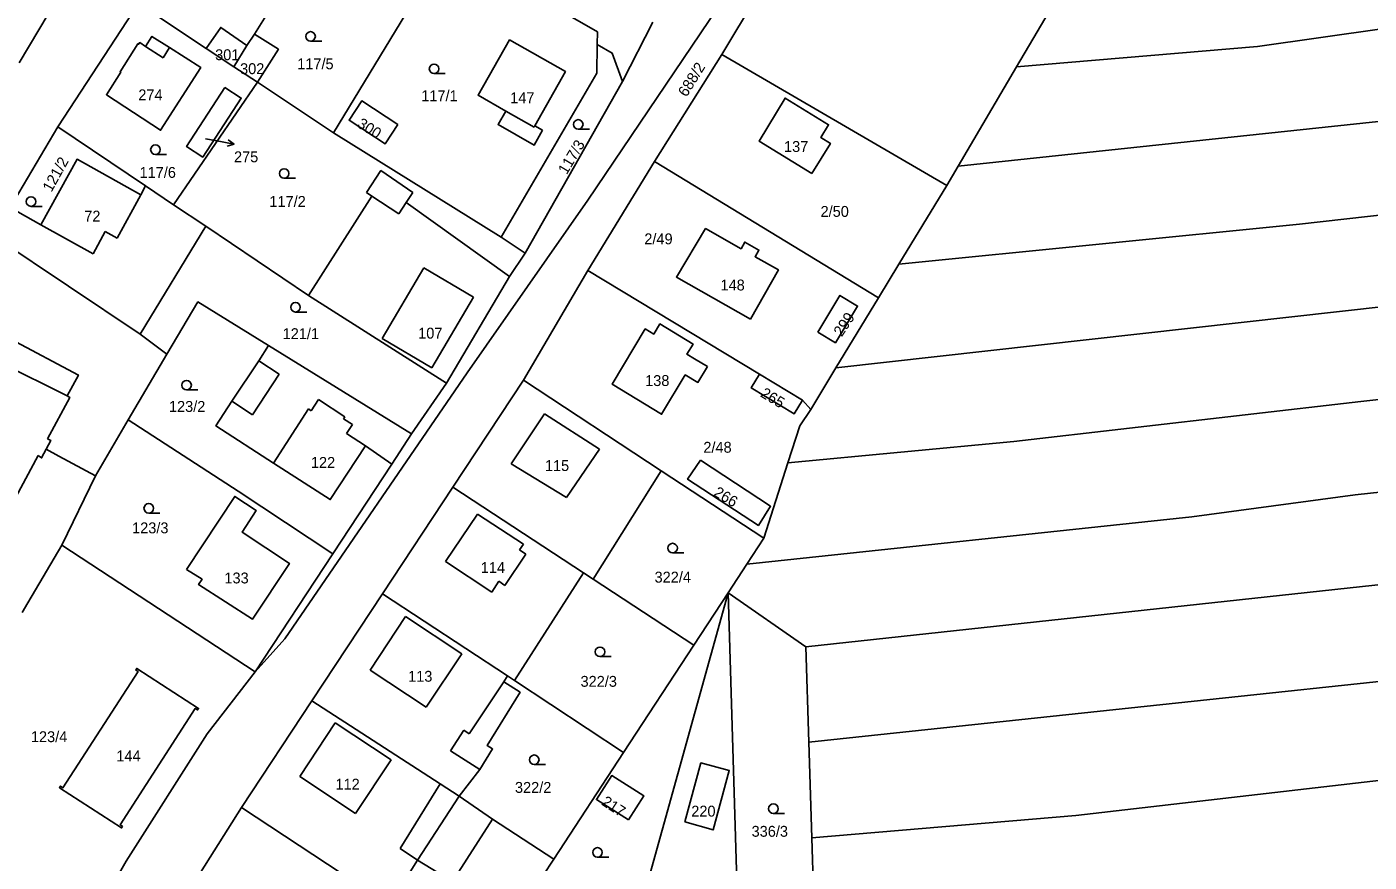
# Model space of a CAD drawing. Extents: x -7483133 to -743907, y -11317770 to -1129777.
# Drawn here: x -746337 to -746127.1, y -1131956.4 to -1131825.9 of the extents above; entities that cross this region are included whole.
import ezdxf

# ---------------------------------------------------------------- set-up
doc = ezdxf.new("R2010")
doc.units = 0
for name, color, linetype in [('Hranice parcel', 7, 'Continuous'), ('Parcelní čísla', 7, 'Continuous'), ('Pop  PČ popisy', 7, 'Continuous'), ('Vnitřní kresba', 7, 'Continuous'), ('Značky kultur', 7, 'Continuous')]:
    doc.layers.add(name, color=color, linetype=linetype)

msp = doc.modelspace()

# ---------------------------------------------------------------- linework, layer by layer
at = {"layer": 'Hranice parcel'}
for p, q in [((-746209.77, -1131799.39), (-746228.3, -1131830.15)), ((-746301.39, -1131826.98), (-746286.89, -1131803.83)), ((-746271.26, -1131813.15), (-746289.03, -1131842.41)), ((-746338.17, -1131831.49), (-746329.51, -1131817)), ((-746182.24, -1131832.12), (-746173.02, -1131816.46)), ((-746319.5, -1131822.22), (-746332.13, -1131841.46)), ((-746319.5, -1131822.22), (-746308.91, -1131829.22)), ((-746243.86, -1131834.4), (-746239.12, -1131825.11)), ((-746302.57, -1131828.75), (-746301.39, -1131826.98)), ((-746304.59, -1131832.1), (-746308.91, -1131829.22)), ((-746304.59, -1131832.1), (-746302.57, -1131828.75)), ((-746228.3, -1131830.15), (-746238.83, -1131846.91)), ((-746228.3, -1131830.15), (-746193.13, -1131850.62)), ((-746300.9, -1131834.52), (-746304.59, -1131832.1)), ((-746191.35, -1131847.6), (-746182.24, -1131832.12)), ((-746300.9, -1131834.52), (-746314.01, -1131853.67)), ((-746289.03, -1131842.41), (-746300.9, -1131834.52)), ((-746259.04, -1131861.19), (-746243.86, -1131834.4)), ((-746332.13, -1131841.46), (-746339.57, -1131854.09)), ((-746332.13, -1131841.46), (-746318.41, -1131850.71)), ((-746289.03, -1131842.41), (-746262.8, -1131858.73)), ((-746238.83, -1131846.91), (-746249.25, -1131863.91)), ((-746203.84, -1131868.19), (-746238.83, -1131846.91)), ((-746193.13, -1131850.62), (-746191.35, -1131847.6)), ((-746318.41, -1131850.71), (-746319.14, -1131852.08)), ((-746314.01, -1131853.67), (-746318.41, -1131850.71)), ((-746200.63, -1131862.93), (-746193.13, -1131850.62)), ((-746308.95, -1131856.97), (-746314.01, -1131853.67)), ((-746334.77, -1131856.76), (-746339.57, -1131854.09)), ((-746319.24, -1131873.86), (-746308.95, -1131856.97)), ((-746308.95, -1131856.97), (-746292.9, -1131867.8)), ((-746342.22, -1131858.51), (-746319.24, -1131873.86)), ((-746259.04, -1131861.19), (-746262.8, -1131858.73)), ((-746261.5, -1131864.88), (-746259.04, -1131861.19)), ((-746249.25, -1131863.91), (-746259.34, -1131881.05)), ((-746222.41, -1131880.1), (-746249.25, -1131863.91)), ((-746203.84, -1131868.19), (-746200.63, -1131862.93)), ((-746271.33, -1131881.54), (-746261.5, -1131864.88)), ((-746292.9, -1131867.8), (-746271.33, -1131881.54)), ((-746210.48, -1131879.13), (-746203.84, -1131868.19)), ((-746319.24, -1131873.86), (-746315.09, -1131877.01)), ((-746299.17, -1131875.66), (-746300.71, -1131878.01)), ((-746276.83, -1131889.45), (-746299.17, -1131875.66)), ((-746315.09, -1131877.01), (-746321.11, -1131887.27)), ((-746259.34, -1131881.05), (-746270.35, -1131897.75)), ((-746237.77, -1131895.22), (-746259.34, -1131881.05)), ((-746222.41, -1131880.1), (-746215.69, -1131884.18)), ((-746214.41, -1131885.62), (-746210.48, -1131879.13)), ((-746276.83, -1131889.45), (-746271.33, -1131881.54)), ((-746214.41, -1131885.62), (-746215.69, -1131884.18)), ((-746321.11, -1131887.27), (-746326.24, -1131896.01)), ((-746279.91, -1131894.16), (-746276.83, -1131889.45)), ((-746284.04, -1131891.32), (-746279.91, -1131894.16)), ((-746289.1, -1131908.18), (-746279.91, -1131894.16)), ((-746248.44, -1131912.14), (-746237.77, -1131895.22)), ((-746237.77, -1131895.22), (-746221.73, -1131905.75)), ((-746221.73, -1131905.75), (-746217.97, -1131893.97)), ((-746326.24, -1131896.01), (-746331.51, -1131906.85)), ((-746270.35, -1131897.75), (-746281.37, -1131914.44)), ((-746249.95, -1131911.15), (-746270.35, -1131897.75)), ((-746224.39, -1131909.81), (-746221.73, -1131905.75)), ((-746331.51, -1131906.85), (-746301.25, -1131926.61)), ((-746301.25, -1131926.61), (-746289.1, -1131908.18)), ((-746227.34, -1131914.3), (-746224.39, -1131909.81)), ((-746260.73, -1131927.99), (-746249.95, -1131911.15)), ((-746249.95, -1131911.15), (-746248.44, -1131912.14)), ((-746232.7, -1131922.48), (-746248.44, -1131912.14)), ((-746281.37, -1131914.44), (-746292.38, -1131931.14)), ((-746261.82, -1131927.27), (-746281.37, -1131914.44)), ((-746227.34, -1131914.3), (-746245.46, -1131979.36)), ((-746227.34, -1131914.3), (-746232.7, -1131922.48)), ((-746215.18, -1131922.7), (-746227.34, -1131914.3)), ((-746227.34, -1131914.3), (-746225.16, -1131986.13)), ((-746232.7, -1131922.48), (-746243.67, -1131939.2)), ((-746214.71, -1131937.61), (-746215.18, -1131922.7)), ((-746261.82, -1131927.27), (-746260.73, -1131927.99)), ((-746243.67, -1131939.2), (-746260.73, -1131927.99)), ((-746292.38, -1131931.14), (-746303.39, -1131947.83)), ((-746214.24, -1131952.56), (-746214.71, -1131937.61)), ((-746243.67, -1131939.2), (-746254.59, -1131955.91)), ((-746264.16, -1131949.64), (-746269.36, -1131946.03)), ((-746303.39, -1131947.83), (-746309.81, -1131957.99)), ((-746303.39, -1131947.83), (-746280.26, -1131963.02)), ((-746264.16, -1131949.64), (-746254.59, -1131955.91)), ((-746213.8, -1131966.46), (-746214.24, -1131952.56)), ((-746254.59, -1131955.91), (-746265.61, -1131972.65))]:
    msp.add_line(p, q, dxfattribs=at)
for points in [[(-746154.22, -1131685.29), (-746175.35, -1131725.88), (-746198.19, -1131767.85), (-746214.17, -1131798.54), (-746227.58, -1131820.8), (-746249.27, -1131852.92), (-746268.11, -1131879.9), (-746296.61, -1131921.49), (-746301.25, -1131926.61)], [(-746182.24, -1131832.12), (-746144.56, -1131828.9), (-746105.32, -1131823.34), (-745952.05, -1131805.35), (-745871.83, -1131797.13)], [(-746191.35, -1131847.6), (-746119.75, -1131839.99), (-746065.09, -1131833.14), (-745871.36, -1131811.65)], [(-746271.26, -1131813.15), (-746247.77, -1131826.64), (-746247.79, -1131828.59)], [(-746308.91, -1131829.22), (-746306.65, -1131825.94), (-746302.57, -1131828.75)], [(-745870.88, -1131826.3), (-745979.48, -1131837.99), (-746072.36, -1131849.26), (-746138, -1131856.68), (-746200.63, -1131862.93)], [(-746314.64, -1131829.08), (-746309.76, -1131832.23), (-746316.05, -1131842), (-746324.52, -1131836.47), (-746322.27, -1131832.95), (-746322.39, -1131832.87), (-746319.59, -1131828.5), (-746319.48, -1131828.58), (-746319.31, -1131828.31), (-746318.38, -1131828.91), (-746317.39, -1131827.36), (-746314.64, -1131829.08)], [(-746301.39, -1131826.98), (-746297.63, -1131829.35), (-746300.9, -1131834.52)], [(-746256.34, -1131841.99), (-746257.55, -1131841.31), (-746252.77, -1131832.83), (-746261.49, -1131827.9), (-746266.42, -1131836.53), (-746262.09, -1131839.01), (-746263.3, -1131841.12), (-746257.66, -1131844.34), (-746256.34, -1131841.99)], [(-746262.8, -1131858.73), (-746247.85, -1131833.09), (-746247.79, -1131828.59)], [(-746247.79, -1131828.59), (-746245.47, -1131829.94), (-746243.86, -1131834.4)], [(-746306, -1131835.32), (-746303.44, -1131836.98), (-746309.45, -1131846.21), (-746311.99, -1131844.56), (-746306, -1131835.32)], [(-746214.22, -1131848.78), (-746211.33, -1131844.06), (-746212.84, -1131843.13), (-746211.63, -1131841.15), (-746218.42, -1131836.98), (-746222.48, -1131843.71), (-746214.22, -1131848.78)], [(-746278.97, -1131841.12), (-746280.93, -1131844.12), (-746286.58, -1131840.44), (-746284.6, -1131837.42), (-746278.97, -1131841.12)], [(-746210.48, -1131879.13), (-746068.37, -1131863.25), (-745959.35, -1131849.97), (-745888.43, -1131842.13), (-745871.39, -1131840.43)], [(-746319.14, -1131852.08), (-746329.09, -1131846.55), (-746334.77, -1131856.76)], [(-746276.62, -1131851.71), (-746281.61, -1131848.31), (-746283.86, -1131851.75)], [(-746283.86, -1131851.75), (-746283.01, -1131852.31), (-746292.9, -1131867.8)], [(-746261.5, -1131864.88), (-746277.66, -1131853.3), (-746276.62, -1131851.71)], [(-746217.97, -1131893.97), (-746182.66, -1131890.66), (-746128.44, -1131884.38), (-745994.6, -1131869.54), (-745871.94, -1131855.43)], [(-746223.85, -1131871.53), (-746219.47, -1131863.84), (-746223.11, -1131861.77), (-746222.52, -1131860.73), (-746224.72, -1131859.48), (-746225.31, -1131860.52), (-746230.84, -1131857.37), (-746235.4, -1131864.95), (-746223.85, -1131871.53)], [(-746213.32, -1131873.54), (-746209.86, -1131867.8), (-746207.08, -1131869.48), (-746210.56, -1131875.2), (-746213.32, -1131873.54)], [(-746315.09, -1131877.01), (-746310.22, -1131868.84), (-746299.17, -1131875.66)], [(-746230.56, -1131878.94), (-746232.57, -1131877.72), (-746233.76, -1131877), (-746232.8, -1131875.41), (-746238, -1131872.27), (-746238.96, -1131873.85), (-746240.28, -1131873.05), (-746245.45, -1131881.7), (-746237.74, -1131886.38), (-746234.02, -1131880.23), (-746232.06, -1131881.41), (-746230.56, -1131878.94)], [(-746224.39, -1131909.81), (-746154.83, -1131902.38), (-746129.29, -1131898.95), (-745983.18, -1131883.12), (-745872.95, -1131870.82)], [(-746333.74, -1131890.21), (-746330.25, -1131883.74), (-746330.66, -1131883.52), (-746328.89, -1131880.25), (-746339.47, -1131874.63), (-746341.38, -1131878.14), (-746340.94, -1131878.38), (-746343.79, -1131883.58), (-746344.46, -1131884.81), (-746344.04, -1131885.02), (-746344.6, -1131886.06)], [(-746300.71, -1131878.01), (-746304.91, -1131884.36), (-746307.41, -1131888.2), (-746298.37, -1131894.02), (-746289.52, -1131899.71), (-746284.04, -1131891.32)], [(-746215.69, -1131884.18), (-746216.98, -1131886.31), (-746223.7, -1131882.26), (-746222.41, -1131880.1)], [(-746344.6, -1131886.06), (-746345.17, -1131887.1), (-746345.57, -1131886.87), (-746346.84, -1131889.17), (-746349.1, -1131893.27), (-746349.5, -1131893.05), (-746351.45, -1131896.64), (-746340.87, -1131902.35), (-746339.07, -1131899.09), (-746338.66, -1131899.32), (-746335.16, -1131892.84)], [(-746321.11, -1131887.27), (-746303.92, -1131898.42), (-746289.1, -1131908.18)], [(-746217.97, -1131893.97), (-746216.12, -1131888.19), (-746214.41, -1131885.62)], [(-746215.18, -1131922.7), (-746100.74, -1131910.33), (-745986.39, -1131897.96), (-745877.23, -1131886.38)], [(-746333.93, -1131891.84), (-746333.2, -1131890.49), (-746333.74, -1131890.21)], [(-746335.16, -1131892.84), (-746334.66, -1131893.21), (-746333.93, -1131891.84)], [(-746326.24, -1131896.01), (-746331.96, -1131892.91), (-746333.93, -1131891.84)], [(-746231.67, -1131893.56), (-746220.68, -1131900.75), (-746222.59, -1131903.76), (-746233.66, -1131896.54), (-746231.67, -1131893.56)], [(-746311.99, -1131910.64), (-746309.57, -1131912.15), (-746310.11, -1131912.99), (-746301.69, -1131918.41), (-746295.92, -1131909.68), (-746303.31, -1131904.8), (-746301.09, -1131901.44), (-746304.45, -1131899.22), (-746311.99, -1131910.64)], [(-745881.66, -1131902.09), (-746058.97, -1131921.07), (-746214.71, -1131937.61)], [(-746331.51, -1131906.85), (-746336.79, -1131915.84), (-746337.68, -1131917.35)], [(-746214.24, -1131952.56), (-746172.98, -1131949.05), (-746087.79, -1131939.2), (-745987.44, -1131929), (-745886.79, -1131918.79)], [(-746321.98, -1131950.76), (-746322.36, -1131950.51), (-746310.64, -1131932.34), (-746310.26, -1131932.58), (-746310.1, -1131932.33), (-746319.78, -1131926.09), (-746319.94, -1131926.34), (-746319.57, -1131926.59), (-746331.31, -1131944.72), (-746331.69, -1131944.48), (-746331.85, -1131944.73), (-746322.14, -1131951.01), (-746321.98, -1131950.76)], [(-746327.57, -1131966.94), (-746321.42, -1131956.19), (-746308.76, -1131936.3), (-746301.25, -1131926.61)], [(-746269.36, -1131946.03), (-746266.16, -1131941.89), (-746264.15, -1131938.66), (-746265.01, -1131938.12), (-746259.86, -1131929.82), (-746262.41, -1131928.16), (-746261.82, -1131927.27)], [(-746269.36, -1131946.03), (-746272.34, -1131944.1), (-746292.38, -1131931.14)], [(-746234.08, -1131950.08), (-746229.68, -1131951.33), (-746227.16, -1131942.04), (-746231.58, -1131940.84), (-746234.08, -1131950.08)], [(-746242.9, -1131949.76), (-746240.5, -1131946.01), (-746245.53, -1131942.83), (-746247.91, -1131946.58), (-746242.9, -1131949.76)], [(-746280.26, -1131963.02), (-746275.86, -1131956.03), (-746270.43, -1131959.39), (-746264.16, -1131949.64)]]:
    msp.add_lwpolyline(points, dxfattribs=at)
at = {"layer": 'Pop  PČ popisy'}
for p, q in [((-746309.01, -1131843.33), (-746307.52, -1131843.62)), ((-746307.52, -1131843.62), (-746304.57, -1131844.19)), ((-746304.57, -1131844.19), (-746305.65, -1131844.49)), ((-746304.57, -1131844.19), (-746305.46, -1131843.51))]:
    msp.add_line(p, q, dxfattribs=at)
at = {"layer": 'Vnitřní kresba'}
for p, q in [((-746318.38, -1131828.91), (-746315.65, -1131830.67)), ((-746315.65, -1131830.67), (-746314.64, -1131829.08)), ((-746262.09, -1131839.01), (-746257.67, -1131841.53)), ((-746257.67, -1131841.53), (-746257.55, -1131841.31)), ((-746319.14, -1131852.08), (-746322.82, -1131858.89)), ((-746278.82, -1131855.06), (-746283.01, -1131852.31)), ((-746277.66, -1131853.3), (-746278.82, -1131855.06)), ((-746334.77, -1131856.76), (-746326.58, -1131861.31)), ((-746326.58, -1131861.31), (-746324.71, -1131857.84)), ((-746324.71, -1131857.84), (-746322.82, -1131858.89)), ((-746281.41, -1131874.57), (-746274.92, -1131863.52)), ((-746274.92, -1131863.52), (-746267.15, -1131868.08)), ((-746267.15, -1131868.08), (-746273.64, -1131879.13)), ((-746273.64, -1131879.13), (-746281.41, -1131874.57)), ((-746330.66, -1131883.52), (-746340.94, -1131878.38)), ((-746300.71, -1131878.01), (-746297.49, -1131880.14)), ((-746297.49, -1131880.14), (-746301.69, -1131886.49)), ((-746301.69, -1131886.49), (-746304.91, -1131884.36)), ((-746292.5, -1131885.82), (-746291.38, -1131884.1)), ((-746291.38, -1131884.1), (-746287.25, -1131886.78)), ((-746298.37, -1131894.02), (-746292.92, -1131885.55)), ((-746292.92, -1131885.55), (-746292.5, -1131885.82)), ((-746287.25, -1131886.78), (-746287.45, -1131887.07)), ((-746287.45, -1131887.07), (-746286.06, -1131887.97)), ((-746261.22, -1131894.12), (-746256.01, -1131886.33)), ((-746256.01, -1131886.33), (-746247.44, -1131891.83)), ((-746286.06, -1131887.97), (-746286.99, -1131889.41)), ((-746286.99, -1131889.41), (-746284.04, -1131891.32)), ((-746247.44, -1131891.83), (-746252.58, -1131899.4)), ((-746252.58, -1131899.4), (-746261.22, -1131894.12)), ((-746271.5, -1131909.4), (-746266.5, -1131901.97)), ((-746266.5, -1131901.97), (-746259.29, -1131906.68)), ((-746258.93, -1131908.26), (-746262.22, -1131913.11)), ((-746259.29, -1131906.68), (-746259.93, -1131907.54)), ((-746259.93, -1131907.54), (-746258.93, -1131908.26)), ((-746264.29, -1131914.18), (-746271.5, -1131909.4)), ((-746263.15, -1131912.47), (-746264.29, -1131914.18)), ((-746262.22, -1131913.11), (-746263.15, -1131912.47)), ((-746283.28, -1131926.35), (-746277.74, -1131917.99)), ((-746277.74, -1131917.99), (-746268.96, -1131923.79)), ((-746268.96, -1131923.79), (-746274.53, -1131932.15)), ((-746274.53, -1131932.15), (-746283.28, -1131926.35)), ((-746267.82, -1131936.32), (-746262.41, -1131928.16)), ((-746288.75, -1131934.6), (-746294.29, -1131942.98)), ((-746280.02, -1131940.37), (-746288.75, -1131934.6)), ((-746270.75, -1131938.96), (-746268.62, -1131935.76)), ((-746268.62, -1131935.76), (-746267.82, -1131936.32)), ((-746266.16, -1131941.89), (-746270.75, -1131938.96)), ((-746285.56, -1131948.75), (-746280.02, -1131940.37)), ((-746294.29, -1131942.98), (-746285.56, -1131948.75)), ((-746278.57, -1131954.25), (-746272.34, -1131944.1)), ((-746275.86, -1131956.03), (-746269.36, -1131946.03)), ((-746275.86, -1131956.03), (-746278.57, -1131954.25))]:
    msp.add_line(p, q, dxfattribs=at)
at = {"layer": 'Značky kultur'}
for p, q in [((-746292.6, -1131828.1), (-746290.85, -1131828.1)), ((-746273.29, -1131833.16), (-746271.54, -1131833.16)), ((-746250.76, -1131841.85), (-746249.01, -1131841.85)), ((-746316.85, -1131845.79), (-746315.1, -1131845.79)), ((-746296.73, -1131849.52), (-746294.98, -1131849.52)), ((-746336.3, -1131853.9), (-746334.55, -1131853.9)), ((-746294.96, -1131870.41), (-746293.21, -1131870.41)), ((-746311.99, -1131882.58), (-746310.24, -1131882.58)), ((-746317.89, -1131901.82), (-746316.14, -1131901.82)), ((-746236.01, -1131908.04), (-746234.26, -1131908.04)), ((-746247.36, -1131924.25), (-746245.61, -1131924.25)), ((-746257.64, -1131941.11), (-746255.89, -1131941.11)), ((-746220.25, -1131948.76), (-746218.5, -1131948.76)), ((-746247.75, -1131955.59), (-746246, -1131955.59))]:
    msp.add_line(p, q, dxfattribs=at)
for centre in [(-746292.6, -1131827.35), (-746273.29, -1131832.41), (-746250.76, -1131841.1), (-746316.85, -1131845.04), (-746296.73, -1131848.77), (-746336.3, -1131853.15), (-746294.96, -1131869.66), (-746311.99, -1131881.83), (-746317.89, -1131901.07), (-746236.01, -1131907.29), (-746247.36, -1131923.5), (-746257.64, -1131940.36), (-746220.25, -1131948.01), (-746247.75, -1131954.84)]:
    msp.add_circle(centre, 0.75, dxfattribs=at)

# ---------------------------------------------------------------- texts
at = {"layer": 'Parcelní čísla'}
for s, p in [('301', (-746307.52, -1131831.06)), ('117/5', (-746294.69, -1131832.48)), ('302', (-746303.62, -1131833.24)), ('274', (-746319.53, -1131837.33)), ('117/1', (-746275.3, -1131837.47)), ('147', (-746261.4, -1131837.78)), ('275', (-746304.57, -1131847.01)), ('137', (-746218.59, -1131845.4)), ('117/6', (-746319.34, -1131849.45)), ('117/2', (-746299.04, -1131853.98)), ('2/50', (-746212.88, -1131855.54)), ('72', (-746327.98, -1131856.28)), ('2/49', (-746240.43, -1131859.83)), ('148', (-746228.52, -1131867.04)), ('121/1', (-746296.97, -1131874.64)), ('107', (-746275.78, -1131874.56)), ('138', (-746240.3, -1131881.97)), ('123/2', (-746314.74, -1131886.01)), ('2/48', (-746231.2, -1131892.39)), ('122', (-746292.55, -1131894.76)), ('115', (-746255.97, -1131895.25)), ('123/3', (-746320.5, -1131904.98)), ('114', (-746266, -1131911.18)), ('133', (-746306.07, -1131912.81)), ('322/4', (-746238.83, -1131912.68)), ('113', (-746277.35, -1131928.17)), ('322/3', (-746250.4, -1131928.96)), ('123/4', (-746336.32, -1131937.61)), ('144', (-746322.96, -1131940.61)), ('112', (-746288.71, -1131945.03)), ('322/2', (-746260.65, -1131945.53)), ('220', (-746233.09, -1131949.24)), ('336/3', (-746223.66, -1131952.39))]:
    msp.add_text(s, height=1.7, dxfattribs=at).set_placement(p)
for s, rotation, p in [('688/2', 58, (-746233.84, -1131836.92)), ('300', 328, (-746285.44, -1131841.41)), ('117/3', 59, (-746252.57, -1131849.05)), ('121/2', 61, (-746333.11, -1131851.78)), ('299', 56, (-746209.57, -1131874.36)), ('265', 329, (-746222.4, -1131883.55)), ('266', 329, (-746229.73, -1131899.02)), ('217', 327, (-746247.26, -1131947.31))]:
    msp.add_text(s, height=1.7, rotation=rotation, dxfattribs=at).set_placement(p)

doc.saveas('drawing.dxf')
